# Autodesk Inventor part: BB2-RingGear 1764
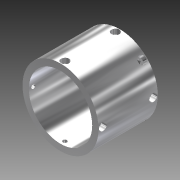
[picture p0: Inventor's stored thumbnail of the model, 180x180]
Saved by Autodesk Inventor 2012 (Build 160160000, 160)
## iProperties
Company: FirstCadLibrary
Shininess: 64.0
Length Units: 11269
Angle Units: 11279
Time Units: 11290
Mass Units: 11283
Length Display Precision: 3
Angle Display Precision: 2
Compacted: True
Part Number: BB2-RingGear 1764
Document SubType Name: Modeling
Created: 2007-01
Designer: Ed Sparks
Material: Steel, Mild
Catalog Web Link: www.banebots.com
Vendor: BaneBots
Mass: 305.335 g
Surface Area: 187.703 cm^2
Volume: 38.8467 cm^3
Density: 7.86 g/cm^3
Density: 0.0
Volumn: 0.0
Area: 0.0
PropertySet Name: Model Information
Control State: 0
Master: False
Checked Out: False
Author: Ed Sparks
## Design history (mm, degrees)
sketch "Sketch1"
  geometry: C1 r 25 at (0, 0); C2 r 30 at (0, 0); 1 further point
  constraints: 2 centre point, 2 coincident, 1 concentric, 1 other
  dimensions: "d0" = 50 diameter of C1; "d1" = 60 diameter of C2
extrude "Extrusion1" new body sketch "Sketch1" distance "d2" = 46.8; taper "d3" = 0 deg
workplane "Work Plane1"
sketch "Sketch3"
  geometry: L1 (-30, 0)-(30, 0) reference; L2 (0, 0)-(0, 28.195); 1 further point
  constraints: 2 end point, 1 midpoint, 1 perpendicular, 1 point on line
  dimensions: "d5" = 3.5 distance from line of L1 point (0, 3.5)
hole "Hole1" sketch "Sketch3" at (0, 3.5) diameter "d6" = 3.2; stored, may be unused: countersink angle "d10" = 82 deg, drill point angle "d12" = 118 deg; dims "d7" = 6, "d8" = 6.2, "d9" = 4.2, "d11" = 8
pattern_circular "Circular Pattern1" dims angle "d15" = 360 deg
sketch "Sketch4"
  geometry: L1 (-30, 46.8)-(30, 46.8) reference; L2 (0, 46.8)-(0, 26.14); 1 further point
  constraints: 2 end point, 1 midpoint, 1 perpendicular, 1 point on line
  dimensions: "d16" = 3.5 distance from line of L1 point (0, 43.3)
hole "Hole2" sketch "Sketch4" at (0, 43.3) diameter "d17" = 3.2; stored, may be unused: countersink angle "d21" = 82 deg, drill point angle "d23" = 118 deg; dims "d18" = 6, "d19" = 6.2, "d20" = 4.2, "d22" = 8
pattern_circular "Circular Pattern2" dims angle "d26" = 360 deg
body "Solid1"
